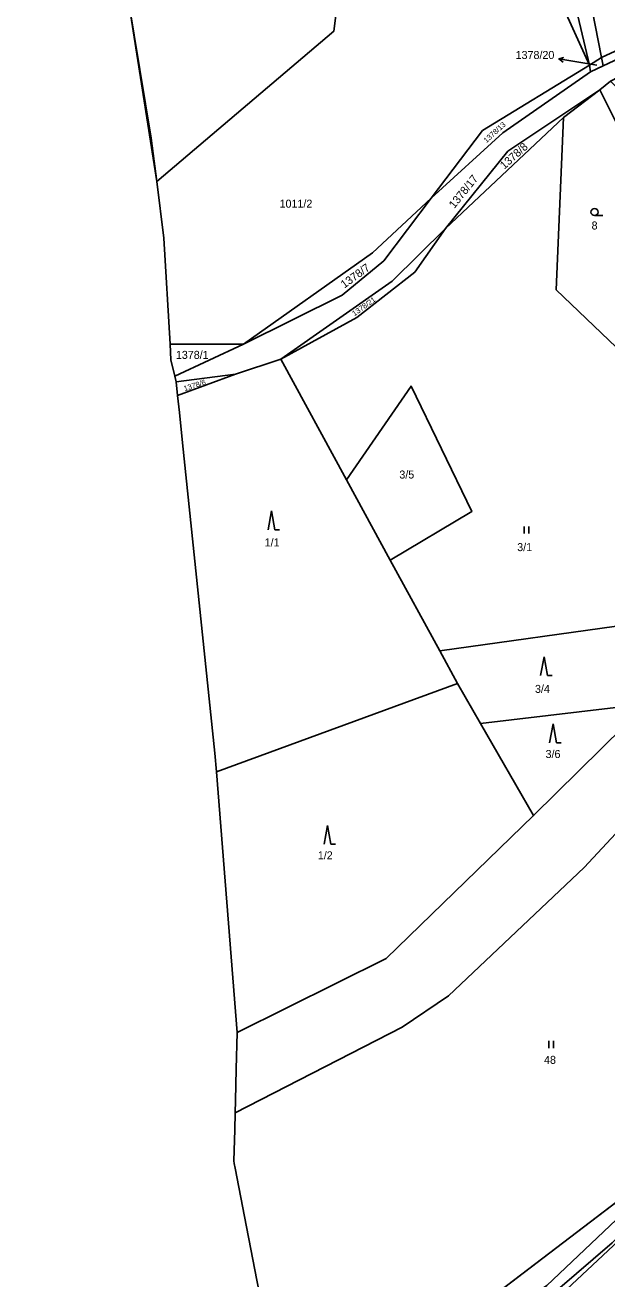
# Model space of a CAD drawing. Extents: x -588699 to -585793, y -1060280 to -1056731.
# Drawn here: x -588467.1 to -588343.5, y -1058381.5 to -1058115.3 of the extents above; entities that cross this region are included whole.
import ezdxf

# ---------------------------------------------------------------- set-up
doc = ezdxf.new("R2010")
doc.units = 0
for name, color, linetype in [('Druh pozemku', 7, 'Continuous'), ('Lesy', 7, 'Continuous'), ('Parcela nároku', 7, 'Continuous'), ('Parcelní číslo', 7, 'Continuous'), ('Vnitřní obvod', 7, 'Continuous'), ('Vnější hranice převzatá', 7, 'Continuous')]:
    doc.layers.add(name, color=color, linetype=linetype)

msp = doc.modelspace()

# ---------------------------------------------------------------- linework, layer by layer
at = {"layer": 'Druh pozemku'}
for p, q in [((-588344.42, -1058155.76), (-588346.17, -1058155.76)), ((-588414.75, -1058218.46), (-588415.48, -1058222.46)), ((-588414.75, -1058218.46), (-588414.02, -1058222.46)), ((-588414.02, -1058222.46), (-588413.02, -1058222.46)), ((-588361.1, -1058221.75), (-588361.1, -1058223.25)), ((-588360.08, -1058223.25), (-588360.08, -1058221.75)), ((-588356.89, -1058249.44), (-588357.62, -1058253.44)), ((-588356.89, -1058249.44), (-588356.16, -1058253.44)), ((-588356.16, -1058253.44), (-588355.16, -1058253.44)), ((-588354.96, -1058263.7), (-588355.7, -1058267.7)), ((-588354.96, -1058263.7), (-588354.23, -1058267.7)), ((-588354.23, -1058267.7), (-588353.23, -1058267.7)), ((-588402.86, -1058285.23), (-588403.59, -1058289.23)), ((-588402.86, -1058285.23), (-588402.13, -1058289.23)), ((-588402.13, -1058289.23), (-588401.13, -1058289.23)), ((-588355.89, -1058331.02), (-588355.89, -1058332.52)), ((-588354.86, -1058332.52), (-588354.86, -1058331.02))]:
    msp.add_line(p, q, dxfattribs=at)
msp.add_circle((-588346.17, -1058155.01), 0.75, dxfattribs=at)
at = {"layer": 'Lesy'}
for p, q in [((-588401.51, -1058116.63), (-588397.81, -1058087.8)), ((-588439.11, -1058148.54), (-588401.51, -1058116.63)), ((-588321.5, -1058349.96), (-588382.69, -1058396.58))]:
    msp.add_line(p, q, dxfattribs=at)
at = {"layer": 'Parcela nároku'}
for points in [[(-588453.26, -1058054.02), (-588451.16, -1058073.18), (-588440.27, -1058139.29), (-588439.11, -1058148.54), (-588401.51, -1058116.63), (-588397.81, -1058087.8), (-588359.94, -1058066.21), (-588356.56, -1058042.23), (-588362.75, -1057999.58), (-588370.81, -1057966.5), (-588372.71, -1057917.38), (-588383.72, -1057865.58), (-588467.05, -1057872.25), (-588463.17, -1057889.9), (-588459.8, -1057921.01), (-588456.31, -1057964.19), (-588455.18, -1058021.15)], [(-588347.34, -1058108.72), (-588344.7, -1058122.22), (-588326.35, -1058113.66), (-588334.59, -1058112.33), (-588338.01, -1058106.78), (-588346.56, -1058050.77), (-588355.38, -1058054.63), (-588358.98, -1058080.9), (-588356.77, -1058093.01)], [(-588359.94, -1058066.21), (-588397.81, -1058087.8), (-588401.51, -1058116.63), (-588439.11, -1058148.54), (-588437.6, -1058160.57), (-588436.28, -1058183.04), (-588420.67, -1058183.06), (-588393.33, -1058163.66), (-588380.84, -1058152.03), (-588369.96, -1058137.69), (-588347.27, -1058123.79), (-588353.6, -1058109.72), (-588362.96, -1058095.84), (-588365.29, -1058079.2)], [(-588365.29, -1058079.2), (-588359.94, -1058066.21), (-588361.73, -1058080.68), (-588359.23, -1058093.11), (-588350.63, -1058109.41), (-588347.27, -1058123.79), (-588353.6, -1058109.72), (-588362.96, -1058095.84)], [(-588323.52, -1058114.21), (-588326.35, -1058113.66), (-588344.7, -1058122.22), (-588344.31, -1058123.97)], [(-588344.31, -1058123.97), (-588344.7, -1058122.22), (-588347.27, -1058123.79), (-588346.99, -1058125.2)], [(-588346.99, -1058125.2), (-588347.27, -1058123.79), (-588369.96, -1058137.69), (-588380.84, -1058152.03), (-588365.65, -1058138.16)], [(-588319.63, -1058129.24), (-588335.53, -1058134.21), (-588342.77, -1058127.18), (-588345.06, -1058129.04), (-588337.11, -1058144.94), (-588337.3, -1058156.47), (-588337.48, -1058167.68), (-588317.32, -1058167.52), (-588317.45, -1058157.1), (-588315.37, -1058157.17), (-588313.88, -1058146.84), (-588317.64, -1058146.91), (-588317.1, -1058139.28), (-588316.55, -1058139.21), (-588316.74, -1058138.59)], [(-588364.6, -1058142.1), (-588377.77, -1058158.52), (-588352.73, -1058134.94), (-588345.06, -1058129.04)], [(-588352.73, -1058134.94), (-588345.06, -1058129.04), (-588337.11, -1058144.94), (-588337.3, -1058156.47), (-588337.48, -1058167.68), (-588328.8, -1058195.91), (-588354.34, -1058171.49)], [(-588328.8, -1058195.91), (-588324.16, -1058198.9), (-588338.48, -1058242.51), (-588379.03, -1058248.19), (-588389.52, -1058228.94), (-588372.19, -1058218.57), (-588385.12, -1058191.96), (-588398.8, -1058211.9), (-588412.77, -1058186.25), (-588396.63, -1058177.41), (-588384.28, -1058167.75), (-588377.77, -1058158.52), (-588352.73, -1058134.94), (-588354.34, -1058171.49)], [(-588420.67, -1058183.06), (-588393.33, -1058163.66), (-588380.84, -1058152.03), (-588390.93, -1058165.33), (-588399.71, -1058172.63)], [(-588389.11, -1058169.67), (-588377.77, -1058158.52), (-588384.28, -1058167.75), (-588396.63, -1058177.41), (-588412.77, -1058186.25)], [(-588436.28, -1058183.04), (-588420.67, -1058183.06), (-588435.25, -1058189.88), (-588436.08, -1058186.37)], [(-588422.39, -1058189.41), (-588434.68, -1058193.99), (-588434.3, -1058197.54), (-588433.64, -1058204), (-588426.77, -1058269.88), (-588426.45, -1058273.89), (-588375.26, -1058255.11), (-588379.03, -1058248.19), (-588389.52, -1058228.94), (-588398.8, -1058211.9), (-588412.77, -1058186.25)], [(-588434.97, -1058191.08), (-588422.39, -1058189.41), (-588434.68, -1058193.99)], [(-588372.19, -1058218.57), (-588385.12, -1058191.96), (-588398.8, -1058211.9), (-588389.52, -1058228.94)], [(-588331.5, -1058255.79), (-588338.48, -1058242.51), (-588379.03, -1058248.19), (-588375.26, -1058255.11), (-588370.39, -1058263.58), (-588335.04, -1058259.4)], [(-588422.02, -1058329.2), (-588426.45, -1058273.89), (-588375.26, -1058255.11), (-588370.39, -1058263.58), (-588359.11, -1058283.17), (-588390.41, -1058313.52)], [(-588370.39, -1058263.58), (-588335.04, -1058259.4), (-588359.11, -1058283.17)], [(-588377.16, -1058321.45), (-588387, -1058328.07), (-588422.47, -1058346.26), (-588422.53, -1058349.9), (-588422.74, -1058356.48), (-588422.64, -1058357.02), (-588422.45, -1058358), (-588420.46, -1058368.28), (-588412.96, -1058407.03), (-588382.69, -1058396.58), (-588321.5, -1058349.96), (-588308.25, -1058334.68), (-588306.58, -1058312.23), (-588305.97, -1058299.95), (-588305.79, -1058296.21), (-588313.29, -1058284.5), (-588317.45, -1058281.91), (-588315.59, -1058280.01), (-588324.47, -1058268.49), (-588348.39, -1058294.15)], [(-588411.37, -1058415.27), (-588411.88, -1058412.63), (-588390.19, -1058405.75), (-588373.47, -1058394.95), (-588356.3, -1058382.96), (-588321.5, -1058349.96), (-588309.35, -1058345.07), (-588289.85, -1058343.41), (-588283.85, -1058339.62), (-588279.64, -1058340.05), (-588275.7, -1058340.46), (-588279.96, -1058342.65), (-588287.72, -1058345.7), (-588307.31, -1058347.54), (-588318.03, -1058351.89), (-588353.16, -1058384.75), (-588390.75, -1058409.05)], [(-588393.35, -1058404.86), (-588382.69, -1058396.58), (-588321.5, -1058349.96), (-588356.3, -1058382.96), (-588373.47, -1058394.95), (-588390.19, -1058405.75), (-588411.88, -1058412.63), (-588412.18, -1058411.08)], [(-588411.37, -1058415.27), (-588390.75, -1058409.05), (-588353.16, -1058384.75), (-588318.03, -1058351.89), (-588312.67, -1058363.81), (-588303.89, -1058376.38), (-588299.09, -1058399.3), (-588300.31, -1058407.3), (-588314.7, -1058437.22), (-588311.14, -1058455.01), (-588355.77, -1058477.5), (-588376.46, -1058483.16), (-588388.17, -1058472.04), (-588382.47, -1058463.49), (-588389.54, -1058443.73), (-588396.44, -1058454.3), (-588401.78, -1058438.01)]]:
    msp.add_lwpolyline(points, close=True, dxfattribs=at)
for points in [[(-588350.63, -1058109.41), (-588347.27, -1058123.79), (-588344.7, -1058122.22), (-588347.34, -1058108.72)], [(-588318.89, -1058114.72), (-588342.77, -1058127.18), (-588345.06, -1058129.04), (-588364.6, -1058142.1), (-588377.77, -1058158.52), (-588389.11, -1058169.67), (-588412.77, -1058186.25), (-588422.39, -1058189.41), (-588434.97, -1058191.08), (-588435.25, -1058189.88), (-588420.67, -1058183.06), (-588399.71, -1058172.63), (-588390.93, -1058165.33), (-588380.84, -1058152.03), (-588365.65, -1058138.16), (-588346.99, -1058125.2), (-588344.31, -1058123.97), (-588323.52, -1058114.21)], [(-588324.47, -1058268.49), (-588348.39, -1058294.15), (-588377.16, -1058321.45), (-588387, -1058328.07), (-588422.47, -1058346.26), (-588422.4, -1058343.65), (-588422.22, -1058336.97), (-588422.02, -1058329.2), (-588390.41, -1058313.52), (-588359.11, -1058283.17), (-588335.04, -1058259.4)]]:
    msp.add_lwpolyline(points, dxfattribs=at)
at = {"layer": 'Parcelní číslo'}
for p, q in [((-588350.78, -1058122.98), (-588353.74, -1058122.5)), ((-588345.68, -1058123.81), (-588350.78, -1058122.98))]:
    msp.add_line(p, q, dxfattribs=at)
msp.add_lwpolyline([(-588352.83, -1058123.15), (-588353.74, -1058122.5), (-588352.67, -1058122.17)], dxfattribs=at)
at = {"layer": 'Vnitřní obvod'}
msp.add_lwpolyline([(-588191.94, -1058269.73), (-588198.97, -1058274.28), (-588212.08, -1058286.24), (-588220.48, -1058295.28), (-588225.45, -1058301.27), (-588230.18, -1058305.31), (-588243.74, -1058314.96), (-588258.25, -1058324.96), (-588268.22, -1058332.75), (-588282.52, -1058341.26), (-588286.56, -1058343.66), (-588293.95, -1058345.35), (-588308.3, -1058346.81), (-588315.88, -1058349.9), (-588320.71, -1058351.87), (-588328.74, -1058359.49), (-588342.46, -1058373.88), (-588354.02, -1058383.85), (-588368.24, -1058393.93), (-588378.63, -1058400.49), (-588387.38, -1058405.6), (-588393.78, -1058408.34), (-588411.62, -1058413.95)], dxfattribs=at)
at = {"layer": 'Vnější hranice převzatá'}
msp.add_line((-588445.72, -1058106.24), (-588439.11, -1058148.54), dxfattribs=at)

# ---------------------------------------------------------------- texts
at = {"layer": 'Parcela nároku'}
for s, height, p in [('1378/20', 0.1, (-588345.92, -1058123.81)), ('1011/2', 1.7, (-588413.03, -1058154.08)), ('8', 1.7, (-588346.79, -1058158.71)), ('1378/1', 1.7, (-588435.04, -1058186.18)), ('3/5', 1.7, (-588387.6, -1058211.59)), ('1/1', 1.7, (-588416.2, -1058226)), ('3/1', 1.7, (-588362.58, -1058227)), ('3/4', 1.7, (-588358.81, -1058257.11)), ('3/6', 1.7, (-588356.56, -1058270.93)), ('1/2', 1.7, (-588404.91, -1058292.45)), ('48', 1.7, (-588356.89, -1058335.88))]:
    msp.add_text(s, height=height, dxfattribs=at).set_placement(p)
for s, height, rotation, p in [('1378/13', 1.14, 42.4832, (-588369.1, -1058140.41)), ('1378/8', 1.7, 41.9896, (-588365.32, -1058146.02)), ('1378/17', 1.7, 51.0885, (-588375.93, -1058154.37)), ('1378/7', 1.7, 36.1145, (-588399.28, -1058171.28)), ('1378/21', 1.14, 35.5377, (-588397.13, -1058177.16)), ('1378/6', 1.14, 17.7456, (-588433.17, -1058193.07))]:
    msp.add_text(s, height=height, rotation=rotation, dxfattribs=at).set_placement(p)
at = {"layer": 'Parcelní číslo'}
msp.add_text('1378/20', height=1.7, dxfattribs=at).set_placement((-588362.92, -1058122.5))

doc.saveas('drawing.dxf')
